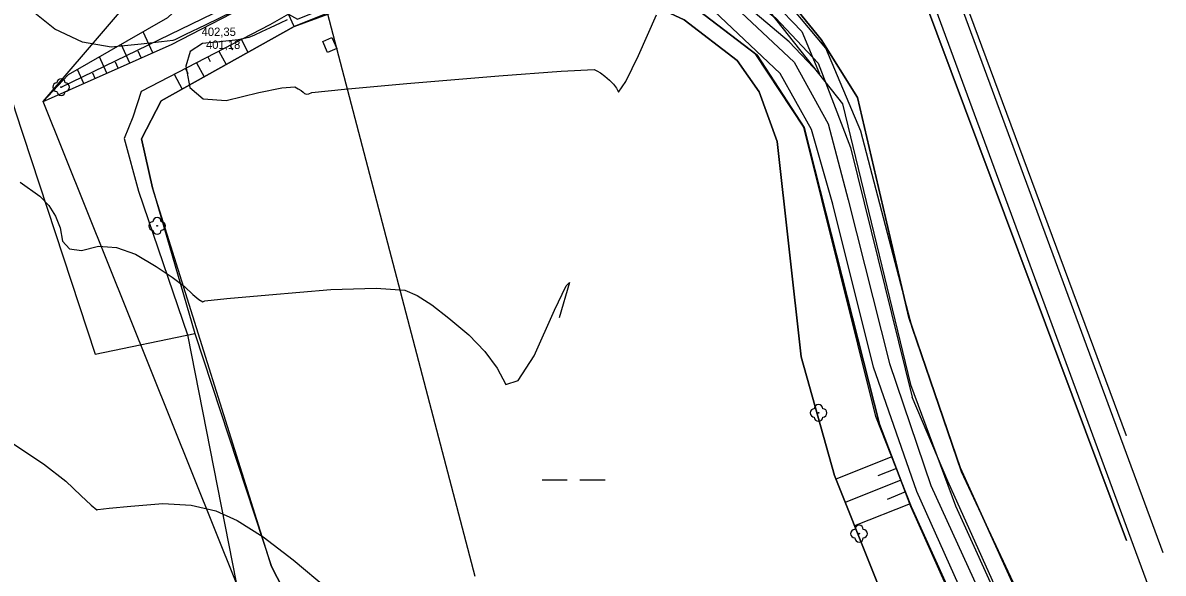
# Model space of a CAD drawing. Extents: x -574342 to -508101, y -1143544 to -1123894.
# Drawn here: x -508450.7 to -508314.7, y -1143399.3 to -1143333.7 of the extents above; entities that cross this region are included whole.
import ezdxf

# ---------------------------------------------------------------- set-up
doc = ezdxf.new("R2010")
doc.units = 0
for name, color, linetype in [('01_PARCELY_NAVRH_PC', 7, 'Continuous'), ('01_PARCELY_NAVRH_VHO', 7, 'Continuous'), ('01_PARCELY_NAVRH_ZPF', 7, 'Continuous'), ('01_PARCELY_NAVRH_ŽP', 7, 'Continuous'), ('05_VHO_V_NÁDRŽ_STAV', 7, 'Continuous'), ('05_VHO_V_TOK_STAV', 7, 'Continuous'), ('42', 7, 'Continuous'), ('43', 7, 'Continuous'), ('51', 7, 'Continuous'), ('54', 7, 'Continuous'), ('55', 7, 'Continuous'), ('57', 7, 'Continuous'), ('60', 7, 'Continuous'), ('61', 7, 'Continuous'), ('cesty', 7, 'Continuous'), ('Level 255', 7, 'Continuous'), ('VRST VEDL', 7, 'Continuous')]:
    doc.layers.add(name, color=color, linetype=linetype)

msp = doc.modelspace()

# ---------------------------------------------------------------- linework, layer by layer
at = {"layer": '01_PARCELY_NAVRH_PC'}
for p, q in [((-508319.1, -1143382.92), (-508319.1, -1143382.92)), ((-508319.1, -1143395.38), (-508319.1, -1143395.38))]:
    msp.add_line(p, q, dxfattribs=at)
msp.add_lwpolyline([(-508319.1, -1143382.92), (-508344.65, -1143314.04), (-508367.51, -1143303.79), (-508380.03, -1143289.33), (-508388.43, -1143262.01), (-508387.45, -1143257.24), (-508381.42, -1143253.61), (-508401.25, -1143255.47), (-508393.61, -1143260.11), (-508380.74, -1143302.76), (-508356.16, -1143314.16), (-508344.92, -1143326.36), (-508319.1, -1143395.38)], dxfattribs=at)
msp.add_lwpolyline([(-508397.53, -1143325.93), (-508394.5, -1143317.14), (-508377.05, -1143323.29), (-508363.05, -1143330.55), (-508352.96, -1143343.32), (-508344.87, -1143376.79), (-508339.52, -1143391.27), (-508327.86, -1143416.88), (-508328.32, -1143431.04), (-508330.46, -1143435.46), (-508335.26, -1143435.36), (-508332.66, -1143429.91), (-508332.21, -1143424.5), (-508336.31, -1143410.38), (-508344.81, -1143391.35), (-508348.55, -1143381.54), (-508357.56, -1143346.15), (-508363.15, -1143337.53), (-508370.86, -1143331.67), (-508380.92, -1143326.77), (-508388.37, -1143325.84)], close=True, dxfattribs=at)
at = {"layer": '01_PARCELY_NAVRH_VHO'}
msp.add_lwpolyline([(-508425.23, -1143400.39), (-508448.26, -1143343.08), (-508432.21, -1143324.29), (-508414.59, -1143317.71), (-508412.73, -1143323), (-508402.47, -1143323.55), (-508397.53, -1143325.93), (-508388.37, -1143325.84), (-508380.92, -1143326.77), (-508370.86, -1143331.67), (-508363.15, -1143337.53), (-508357.56, -1143346.15), (-508348.55, -1143381.54), (-508344.81, -1143391.35), (-508336.31, -1143410.38)], dxfattribs=at)
at = {"layer": '01_PARCELY_NAVRH_ZPF'}
msp.add_line((-508319.1, -1143395.38), (-508319.1, -1143395.38), dxfattribs=at)
msp.add_lwpolyline([(-508319.1, -1143395.38), (-508344.92, -1143326.36), (-508356.16, -1143314.16), (-508380.74, -1143302.76), (-508393.61, -1143260.11), (-508401.25, -1143255.47), (-508414.23, -1143256.72), (-508396.73, -1143306.67), (-508393.87, -1143311.09), (-508388.31, -1143315.9), (-508376.72, -1143318.72), (-508368.91, -1143322.84), (-508361.58, -1143328.14), (-508355.53, -1143335.68), (-508351.18, -1143342.58), (-508345.08, -1143368.8), (-508338.96, -1143386.69), (-508322.95, -1143422.01), (-508319.1, -1143425.74)], dxfattribs=at)
at = {"layer": '01_PARCELY_NAVRH_ŽP'}
for points in [[(-508425.23, -1143400.39), (-508448.26, -1143343.08), (-508432.21, -1143324.29), (-508434.31, -1143320.59), (-508441.9, -1143297.61), (-508445.4, -1143275.01), (-508446.02, -1143260.22), (-508475.11, -1143263.39), (-508493.5, -1143263.3), (-508514.56, -1143259.91), (-508521.01, -1143259.29), (-508524.26, -1143263.08), (-508519.86, -1143267.33), (-508511.25, -1143285.64), (-508506.89, -1143298.29), (-508504.21, -1143312.1), (-508498.26, -1143372.94), (-508491.36, -1143454.58)], [(-508322.95, -1143422.01), (-508338.96, -1143386.69), (-508345.08, -1143368.8), (-508351.18, -1143342.58), (-508355.53, -1143335.68), (-508361.58, -1143328.14)], [(-508363.05, -1143330.55), (-508352.96, -1143343.32), (-508344.87, -1143376.79), (-508339.52, -1143391.27), (-508327.86, -1143416.88)]]:
    msp.add_lwpolyline(points, dxfattribs=at)
at = {"layer": '05_VHO_V_NÁDRŽ_STAV'}
msp.add_lwpolyline([(-508407.31, -1143425.12), (-508421.04, -1143398.5), (-508435.23, -1143353.37), (-508436.55, -1143347.52), (-508434.17, -1143342.98), (-508418.32, -1143334.12), (-508414.31, -1143332.66), (-508412.37, -1143331.74), (-508405, -1143329.35), (-508396.85, -1143328.19), (-508388.18, -1143328.1), (-508381.94, -1143328.58), (-508371.85, -1143333.32), (-508365.54, -1143338.18), (-508362.9, -1143341.9), (-508360.75, -1143347.81), (-508357.9, -1143373.51), (-508353.94, -1143387.64), (-508340.54, -1143421.17)], dxfattribs=at)
at = {"layer": '05_VHO_V_TOK_STAV'}
msp.add_lwpolyline([(-508396.74, -1143399.68), (-508414.31, -1143332.66), (-508430.21, -1143292.19), (-508438.98, -1143265.17), (-508442.91, -1143250.47), (-508445.36, -1143246.6), (-508447.49, -1143245.57), (-508453.89, -1143245.84)], dxfattribs=at)
at = {"layer": '42'}
for points in [[(-508320.88, -1143423.96), (-508327.62, -1143411.06), (-508338.78, -1143387.2), (-508344.67, -1143370.01), (-508350.79, -1143346.58), (-508354.96, -1143336.71), (-508361.36, -1143329.02), (-508368.91, -1143322.84), (-508376.72, -1143318.72), (-508388.31, -1143315.9), (-508393.87, -1143311.09), (-508396.73, -1143306.67), (-508407.7, -1143271.35), (-508414.18, -1143248.41), (-508420.68, -1143216.75), (-508423.64, -1143189.02), (-508427.95, -1143159.6), (-508434.68, -1143117.69), (-508435.01, -1143116.06)], [(-508320.88, -1143423.96), (-508327.62, -1143411.06), (-508338.78, -1143387.2), (-508344.67, -1143370.01), (-508350.79, -1143346.58), (-508354.96, -1143336.71), (-508361.36, -1143329.02), (-508368.91, -1143322.84), (-508376.72, -1143318.72), (-508388.31, -1143315.9), (-508393.87, -1143311.09), (-508396.73, -1143306.67), (-508407.7, -1143271.35), (-508414.18, -1143248.41), (-508420.68, -1143216.75), (-508423.64, -1143189.02), (-508427.95, -1143159.6), (-508434.68, -1143117.69), (-508435.01, -1143116.06)], [(-508495.7, -1143263.7), (-508474.93, -1143263.07), (-508471.38, -1143276.01), (-508468.33, -1143288.58), (-508460.11, -1143315.7), (-508451.61, -1143344.19), (-508442.05, -1143373.19), (-508430.17, -1143370.72)], [(-508495.7, -1143263.7), (-508474.93, -1143263.07), (-508471.38, -1143276.01), (-508468.33, -1143288.58), (-508460.11, -1143315.7), (-508451.61, -1143344.19), (-508442.05, -1143373.19), (-508430.17, -1143370.72)]]:
    msp.add_lwpolyline(points, dxfattribs=at)
at = {"layer": '43'}
for p, q in [((-508388.78, -1143388.15), (-508385.78, -1143388.15)), ((-508384.28, -1143388.15), (-508381.28, -1143388.15))]:
    msp.add_line(p, q, dxfattribs=at)
at = {"layer": '51'}
for points in [[(-508340.68, -1143425.01), (-508340.54, -1143421.17), (-508353.94, -1143387.64), (-508357.9, -1143373.51), (-508360.75, -1143347.81), (-508362.9, -1143341.9), (-508365.54, -1143338.18), (-508371.85, -1143333.32), (-508381.94, -1143328.58), (-508388.18, -1143328.1), (-508396.85, -1143328.19), (-508405, -1143329.35), (-508412.37, -1143331.74)], [(-508340.68, -1143425.01), (-508340.54, -1143421.17), (-508353.94, -1143387.64), (-508357.9, -1143373.51), (-508360.75, -1143347.81), (-508362.9, -1143341.9), (-508365.54, -1143338.18), (-508371.85, -1143333.32), (-508381.94, -1143328.58), (-508388.18, -1143328.1), (-508396.85, -1143328.19), (-508405, -1143329.35), (-508412.37, -1143331.74)], [(-508418.32, -1143334.12), (-508434.17, -1143342.98), (-508436.55, -1143347.52), (-508435.23, -1143353.37), (-508430.17, -1143370.72)], [(-508418.32, -1143334.12), (-508434.17, -1143342.98), (-508436.55, -1143347.52), (-508435.23, -1143353.37), (-508430.17, -1143370.72)], [(-508430.17, -1143370.72), (-508421.04, -1143398.5), (-508407.31, -1143425.12), (-508397.71, -1143443.33), (-508390.39, -1143460.11), (-508385.17, -1143472.92), (-508379.64, -1143474.59), (-508376.84, -1143473.93)], [(-508430.17, -1143370.72), (-508421.04, -1143398.5), (-508407.31, -1143425.12), (-508397.71, -1143443.33), (-508390.39, -1143460.11), (-508385.17, -1143472.92), (-508379.64, -1143474.59), (-508376.84, -1143473.93)]]:
    msp.add_lwpolyline(points, dxfattribs=at)
at = {"layer": '54'}
for centre in [(-508446.12, -1143341.35), (-508434.67, -1143357.89), (-508355.83, -1143380.18), (-508351, -1143394.58)]:
    msp.add_circle(centre, 0.05, dxfattribs=at)
for centre, start, end in [((-508446.62, -1143341.35), 90, 270), ((-508446.12, -1143340.85), 0, 180), ((-508445.62, -1143341.35), 270, 90), ((-508446.12, -1143341.85), 180, 0), ((-508434.67, -1143357.39), 0, 180), ((-508435.17, -1143357.89), 90, 270), ((-508434.67, -1143358.39), 180, 0), ((-508434.17, -1143357.89), 270, 90), ((-508356.33, -1143380.18), 90, 270), ((-508355.83, -1143379.68), 0, 180), ((-508355.33, -1143380.18), 270, 90), ((-508355.83, -1143380.68), 180, 0), ((-508351, -1143394.08), 0, 180), ((-508351.5, -1143394.58), 90, 270), ((-508351, -1143395.08), 180, 0), ((-508350.5, -1143394.58), 270, 90)]:
    msp.add_arc(centre, 0.5, start, end, dxfattribs=at)
at = {"layer": '55'}
for q in [(-508412.54, -1143325.06), (-508412.54, -1143325.06), (-508446.12, -1143341.35), (-508446.12, -1143341.35)]:
    msp.add_line((-508446.12, -1143341.35), q, dxfattribs=at)
for points in [[(-508399.15, -1143318.4), (-508387.42, -1143320.82), (-508372.09, -1143324.77), (-508360.95, -1143333.07), (-508355.89, -1143338.48), (-508352.03, -1143348.55), (-508344.68, -1143378.31)], [(-508399.15, -1143318.4), (-508387.42, -1143320.82), (-508372.09, -1143324.77), (-508360.95, -1143333.07), (-508355.89, -1143338.48), (-508352.03, -1143348.55), (-508344.68, -1143378.31)], [(-508393.66, -1143322.44), (-508382.68, -1143323.47), (-508376.45, -1143325.15), (-508366.92, -1143330.67), (-508358.73, -1143338.39), (-508354.7, -1143345.72), (-508352.28, -1143354.77), (-508347.38, -1143374.29), (-508342.44, -1143388.83), (-508331.65, -1143412.49), (-508329.2, -1143422.38), (-508329.6, -1143428.67), (-508331.43, -1143434.48), (-508334.29, -1143439.6)], [(-508393.66, -1143322.44), (-508382.68, -1143323.47), (-508376.45, -1143325.15), (-508366.92, -1143330.67), (-508358.73, -1143338.39), (-508354.7, -1143345.72), (-508352.28, -1143354.77), (-508347.38, -1143374.29), (-508342.44, -1143388.83), (-508331.65, -1143412.49), (-508329.2, -1143422.38), (-508329.6, -1143428.67), (-508331.43, -1143434.48), (-508334.29, -1143439.6)], [(-508337.06, -1143438.28), (-508334.29, -1143435.16), (-508331.72, -1143428.98), (-508331.25, -1143422.55), (-508333.51, -1143413.22), (-508344.12, -1143389.56), (-508349.28, -1143374.75), (-508354.11, -1143355.29), (-508356.67, -1143346.4), (-508360.4, -1143339.71), (-508368.26, -1143332.28), (-508377.14, -1143327.32), (-508382.88, -1143325.62), (-508393.79, -1143324.58)], [(-508337.06, -1143438.28), (-508334.29, -1143435.16), (-508331.72, -1143428.98), (-508331.25, -1143422.55), (-508333.51, -1143413.22), (-508344.12, -1143389.56), (-508349.28, -1143374.75), (-508354.11, -1143355.29), (-508356.67, -1143346.4), (-508360.4, -1143339.71), (-508368.26, -1143332.28), (-508377.14, -1143327.32), (-508382.88, -1143325.62), (-508393.79, -1143324.58)], [(-508324.83, -1143424.04), (-508328.51, -1143414.82), (-508340.41, -1143388.32), (-508344.68, -1143378.31)], [(-508324.83, -1143424.04), (-508328.51, -1143414.82), (-508340.41, -1143388.32), (-508344.68, -1143378.31)]]:
    msp.add_lwpolyline(points, dxfattribs=at)
at = {"layer": '57'}
msp.add_lwpolyline([(-508416.65, -1143323.34), (-508414.26, -1143326.43), (-508412.93, -1143330.35), (-508412.37, -1143331.74), (-508418.32, -1143334.12), (-508419.02, -1143332.65), (-508417.94, -1143333.24), (-508413.27, -1143331.36), (-508412.93, -1143330.35)], dxfattribs=at)
msp.add_lwpolyline([(-508416.65, -1143323.34), (-508414.26, -1143326.43), (-508412.93, -1143330.35), (-508412.37, -1143331.74), (-508418.32, -1143334.12), (-508419.02, -1143332.65), (-508417.94, -1143333.24), (-508413.27, -1143331.36), (-508412.93, -1143330.35)], dxfattribs=at)
msp.add_lwpolyline([(-508414.9, -1143335.9), (-508413.84, -1143335.44), (-508413.26, -1143336.73), (-508414.36, -1143337.2)], close=True, dxfattribs=at)
msp.add_lwpolyline([(-508414.9, -1143335.9), (-508413.84, -1143335.44), (-508413.26, -1143336.73), (-508414.36, -1143337.2)], close=True, dxfattribs=at)
at = {"layer": '60'}
for points in [[(-508409.76, -1143308.26), (-508402.64, -1143313.55), (-508394.5, -1143317.14), (-508378.66, -1143319), (-508370.76, -1143321.98), (-508364.58, -1143327.7), (-508357.83, -1143334.71), (-508355.73, -1143339.75)], [(-508355.73, -1143339.75), (-508359.33, -1143335.96), (-508366.15, -1143330.14), (-508372.96, -1143325.89), (-508380.12, -1143322.64), (-508395.65, -1143321.1), (-508404.67, -1143315.8), (-508409.76, -1143308.26)], [(-508409.76, -1143308.26), (-508402.64, -1143313.55), (-508394.5, -1143317.14), (-508378.66, -1143319), (-508370.76, -1143321.98), (-508364.58, -1143327.7), (-508357.83, -1143334.71), (-508355.73, -1143339.75)], [(-508355.73, -1143339.75), (-508359.33, -1143335.96), (-508366.15, -1143330.14), (-508372.96, -1143325.89), (-508380.12, -1143322.64), (-508395.65, -1143321.1), (-508404.67, -1143315.8), (-508409.76, -1143308.26)], [(-508422.54, -1143325.03), (-508429.23, -1143329.11), (-508433.43, -1143333.09), (-508445.29, -1143339.87), (-508448.26, -1143343.08)], [(-508422.54, -1143325.03), (-508429.23, -1143329.11), (-508433.43, -1143333.09), (-508445.29, -1143339.87), (-508448.26, -1143343.08)], [(-508338.69, -1143438.96), (-508335.26, -1143435.36), (-508332.63, -1143429.65), (-508332.36, -1143423.38), (-508336.66, -1143409.27), (-508344.75, -1143391.37), (-508349.01, -1143380.62), (-508357.57, -1143346.13), (-508363.29, -1143337.44), (-508371.02, -1143331.59), (-508380.92, -1143326.77), (-508388.37, -1143325.84)], [(-508338.69, -1143438.96), (-508335.26, -1143435.36), (-508332.63, -1143429.65), (-508332.36, -1143423.38), (-508336.66, -1143409.27), (-508344.75, -1143391.37), (-508349.01, -1143380.62), (-508357.57, -1143346.13), (-508363.29, -1143337.44), (-508371.02, -1143331.59), (-508380.92, -1143326.77), (-508388.37, -1143325.84)], [(-508448.26, -1143343.08), (-508432.97, -1143336.26), (-508422.18, -1143330.68), (-508420.38, -1143328.94)], [(-508448.26, -1143343.08), (-508432.97, -1143336.26), (-508422.18, -1143330.68), (-508420.38, -1143328.94)], [(-508419.02, -1143332.65), (-508421.24, -1143333.93), (-508436.57, -1143341.85), (-508437.56, -1143344.93), (-508438.58, -1143347.48), (-508436.88, -1143353.76), (-508431.04, -1143370.87)], [(-508419.02, -1143332.65), (-508421.24, -1143333.93), (-508436.57, -1143341.85), (-508437.56, -1143344.93), (-508438.58, -1143347.48), (-508436.88, -1143353.76), (-508431.04, -1143370.87)], [(-508431.04, -1143370.87), (-508425.23, -1143400.39), (-508409.7, -1143432.51), (-508391.38, -1143484.87)], [(-508431.04, -1143370.87), (-508425.23, -1143400.39), (-508409.7, -1143432.51), (-508391.38, -1143484.87)]]:
    msp.add_lwpolyline(points, dxfattribs=at)
at = {"layer": '61'}
for p, q in [((-508435.2, -1143337.25), (-508436.32, -1143334.74)), ((-508435.2, -1143337.25), (-508436.32, -1143334.74)), ((-508437.94, -1143338.48), (-508438.94, -1143336.24)), ((-508437.94, -1143338.48), (-508438.94, -1143336.24)), ((-508425.97, -1143336.37), (-508425.7, -1143336.89)), ((-508425.97, -1143336.37), (-508425.7, -1143336.89)), ((-508424.63, -1143335.68), (-508423.84, -1143337.21)), ((-508424.63, -1143335.68), (-508423.84, -1143337.21)), ((-508440.68, -1143339.7), (-508441.55, -1143337.73)), ((-508440.68, -1143339.7), (-508441.55, -1143337.73)), ((-508436.57, -1143337.86), (-508436.92, -1143337.07)), ((-508436.57, -1143337.86), (-508436.92, -1143337.07)), ((-508428.63, -1143337.75), (-508428.35, -1143338.3)), ((-508428.63, -1143337.75), (-508428.35, -1143338.3)), ((-508427.3, -1143337.06), (-508426.46, -1143338.67)), ((-508427.3, -1143337.06), (-508426.46, -1143338.67)), ((-508443.42, -1143340.92), (-508444.17, -1143339.23)), ((-508443.42, -1143340.92), (-508444.17, -1143339.23)), ((-508439.31, -1143339.09), (-508439.62, -1143338.39)), ((-508439.31, -1143339.09), (-508439.62, -1143338.39)), ((-508431.3, -1143339.13), (-508431, -1143339.71)), ((-508431.3, -1143339.13), (-508431, -1143339.71)), ((-508429.96, -1143338.44), (-508429.08, -1143340.14)), ((-508429.96, -1143338.44), (-508429.08, -1143340.14)), ((-508442.05, -1143340.31), (-508442.32, -1143339.7)), ((-508442.05, -1143340.31), (-508442.32, -1143339.7)), ((-508432.63, -1143339.81), (-508431.7, -1143341.6)), ((-508432.63, -1143339.81), (-508431.7, -1143341.6)), ((-508347.1, -1143385.43), (-508353.77, -1143388.07)), ((-508347.1, -1143385.43), (-508353.77, -1143388.07)), ((-508346.55, -1143386.82), (-508348.77, -1143387.7)), ((-508346.55, -1143386.82), (-508348.77, -1143387.7)), ((-508346, -1143388.22), (-508352.66, -1143390.85)), ((-508346, -1143388.22), (-508352.66, -1143390.85)), ((-508345.45, -1143389.61), (-508347.66, -1143390.49)), ((-508345.45, -1143389.61), (-508347.66, -1143390.49)), ((-508344.89, -1143391.01), (-508351.54, -1143393.64)), ((-508344.89, -1143391.01), (-508351.54, -1143393.64))]:
    msp.add_line(p, q, dxfattribs=at)
at = {"layer": 'cesty'}
for p, q in [((-508314.74, -1143396.85), (-508340.48, -1143327.13)), ((-508315.51, -1143403.44), (-508343.29, -1143328.16))]:
    msp.add_line(p, q, dxfattribs=at)
at = {"layer": 'VRST VEDL'}
for points in [[(-508425.59, -1143332.32), (-508428.96, -1143333.97), (-508431.29, -1143335.09), (-508432.56, -1143335.7), (-508432.8, -1143335.78), (-508434.14, -1143335.96), (-508436.58, -1143336.23), (-508440.14, -1143336.59), (-508443.57, -1143335.99), (-508446.87, -1143334.42), (-508450.05, -1143331.89)], [(-508419.17, -1143333.32), (-508419.99, -1143333.73), (-508421.2, -1143334.29), (-508422.23, -1143334.76), (-508423.08, -1143335.14), (-508423.75, -1143335.43), (-508425.01, -1143335.69), (-508426.84, -1143335.92), (-508429.26, -1143336.13), (-508430.72, -1143337.11), (-508431.23, -1143338.86), (-508430.79, -1143341.39), (-508429.2, -1143342.76), (-508426.45, -1143342.96), (-508422.56, -1143342), (-508419.82, -1143341.45), (-508418.25, -1143341.3), (-508417.84, -1143341.54), (-508417.51, -1143341.76), (-508417.26, -1143341.95), (-508417.09, -1143342.11), (-508416.87, -1143342.17), (-508416.58, -1143342.13), (-508416.24, -1143341.98), (-508412.35, -1143341.58), (-508404.91, -1143340.91), (-508393.93, -1143339.99), (-508386.49, -1143339.43), (-508382.59, -1143339.23), (-508382.24, -1143339.39), (-508381.82, -1143339.66), (-508381.32, -1143340.04), (-508380.75, -1143340.52), (-508380.28, -1143341), (-508379.93, -1143341.48), (-508379.68, -1143341.96), (-508378.8, -1143340.66), (-508377.29, -1143337.58), (-508375.15, -1143332.72)], [(-508450.98, -1143352.67), (-508448.65, -1143354.34), (-508447.58, -1143355.45), (-508446.78, -1143356.72), (-508446.24, -1143358.14), (-508445.96, -1143359.72), (-508445.11, -1143360.61), (-508443.68, -1143360.81), (-508441.67, -1143360.31), (-508439.52, -1143360.47), (-508437.23, -1143361.27), (-508434.8, -1143362.73), (-508432.86, -1143364.01), (-508431.4, -1143365.13), (-508430.43, -1143366.08), (-508429.7, -1143366.68), (-508429.22, -1143366.93), (-508428.99, -1143366.83), (-508426.37, -1143366.56), (-508421.36, -1143366.11), (-508413.97, -1143365.49), (-508408.56, -1143365.3), (-508405.13, -1143365.54), (-508403.68, -1143366.2), (-508401.93, -1143367.31), (-508399.88, -1143368.87), (-508397.52, -1143370.86), (-508395.61, -1143372.85), (-508394.14, -1143374.84), (-508393.12, -1143376.81), (-508391.64, -1143376.33), (-508389.71, -1143373.37), (-508387.32, -1143367.95), (-508385.92, -1143365.04), (-508385.53, -1143364.64), (-508386.73, -1143368.86)], [(-508451.77, -1143383.91), (-508448.21, -1143386.26), (-508445.54, -1143388.31), (-508443.76, -1143390.04), (-508442.53, -1143391.19), (-508441.86, -1143391.73), (-508441.74, -1143391.68), (-508440.39, -1143391.54), (-508437.81, -1143391.31), (-508434.01, -1143390.99), (-508430.62, -1143391.17), (-508427.66, -1143391.84), (-508425.12, -1143393.02), (-508422.05, -1143394.97), (-508418.44, -1143397.7), (-508414.29, -1143401.2)]]:
    msp.add_lwpolyline(points, dxfattribs=at)

# ---------------------------------------------------------------- texts
at = {"layer": 'Level 255'}
for s, p in [('402,35', (-508429.37, -1143335.25)), ('401,18', (-508428.85, -1143336.79))]:
    msp.add_text(s, height=1, dxfattribs=at).set_placement(p)

doc.saveas('drawing.dxf')
